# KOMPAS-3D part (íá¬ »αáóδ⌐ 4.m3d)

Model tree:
1. Эскиз:1
2. Операция выдавливания:1
     Расстояние 1 = 10
3. Скругление:1
     Радиус = 1
4. Скругление:2
     Радиус = 2
5. Эскиз:2
6. Вырезать элемент выдавливания:1
     Расстояние 1 = 0.2
7. Скругление:3
     Радиус = 0.1
8. Эскиз:3
9. Операция выдавливания:2
     Расстояние 1 = 0.5; Расстояние 2 = 4.9
10. Скругление:4
     Радиус = 0.2
11. Эскиз:4
12. Операция выдавливания:3
     Расстояние 1 = 0.5; Расстояние 2 = 4.9

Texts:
  бак правый 4
  Сплав АЛ8  ГОСТ 1583-93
